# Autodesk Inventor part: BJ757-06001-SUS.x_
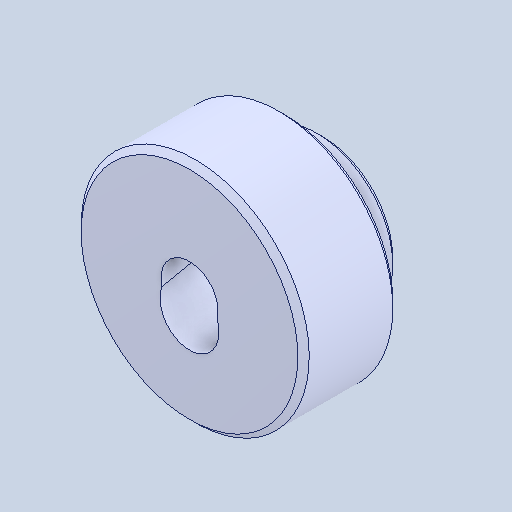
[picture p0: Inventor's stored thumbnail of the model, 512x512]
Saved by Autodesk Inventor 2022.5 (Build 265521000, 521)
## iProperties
Created: 2024-05
Part Number: BJ757-06001-SUS.x_
Material: 一般
Document SubType Name: Modeling
Designer: ImaoCorp
Density: 1 g/cm^3
Appearance: 既定
Author: ImaoCorp
Sending System: SOLIDWORKS 2022-2022290
MC: AMD64
MC_MODEL: Intel64 Family 6 Model 60 Stepping 3, GenuineIntel
OS: Windows_NT
FRU: Parasolid Version 33.1, build 260,  4-25-2022
FORMAT: text
GUISE: transmit
KEY: FILEBJ757-06001-SUS.x_t
DATE: Tue May 21 08:47:11 2024
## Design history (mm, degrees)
feature "Base1"
node "ソリッド1"
